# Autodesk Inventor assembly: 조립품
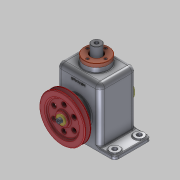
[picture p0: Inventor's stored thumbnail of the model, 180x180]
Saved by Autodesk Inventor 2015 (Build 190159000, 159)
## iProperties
Created: 2023-04
Part Number: 조립품
Document SubType Name: Assembly
Designer: SCD-A08
Author: SCD-A08
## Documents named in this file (20)
- C:\Users\SCD-A08\Desktop\630407V1017\조립품.iam
- C:\Users\SCD-A08\Desktop\630407V1017\본체.ipt
- C:\Users\SCD-A08\Desktop\630407V1017\뒷커버.ipt
- C:\Users\SCD-A08\Desktop\630407V1017\베어링 6205.ipt
- 베어링 6205.ipt
- C:\Users\SCD-A08\Desktop\630407V1017\볼트 M4 x 12.ipt
- C:\Users\SCD-A08\Desktop\630407V1017\V-벨트풀리.ipt
- C:\Users\SCD-A08\Desktop\630407V1017\멈춤링 25 x 1.2.ipt
- 멈춤링 25 x 1.2.ipt
- C:\Users\SCD-A08\Desktop\630407V1017\볼트 M8 x 16.ipt
- C:\Users\SCD-A08\Desktop\630407V1017\앞커버.ipt
- C:\Users\SCD-A08\Desktop\630407V1017\엔드캡.ipt
- C:\Users\SCD-A08\Desktop\630407V1017\오일실 25 40 8.ipt
- 오일실 25 40 8.ipt
- C:\Users\SCD-A08\Desktop\630407V1017\키 6x6x14.ipt
- C:\Users\SCD-A08\Desktop\630407V1017\편심축.ipt
- C:\Users\SCD-A08\Desktop\630407V1017\부시.ipt
- C:\Users\SCD-A08\Desktop\630407V1017\슬라이더.ipt
- C:\Users\SCD-A08\Desktop\630407V1017\윗커버.ipt
- C:\Users\SCD-A08\Desktop\630407V1017\가변스프링.ipt
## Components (2 placed, 2 different names)
1. V-벨트풀리:1 — 각도:1
2. 가변스프링:1
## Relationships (1: Angle 1)
- 각도:1 [Angle]: V-벨트풀리:1
